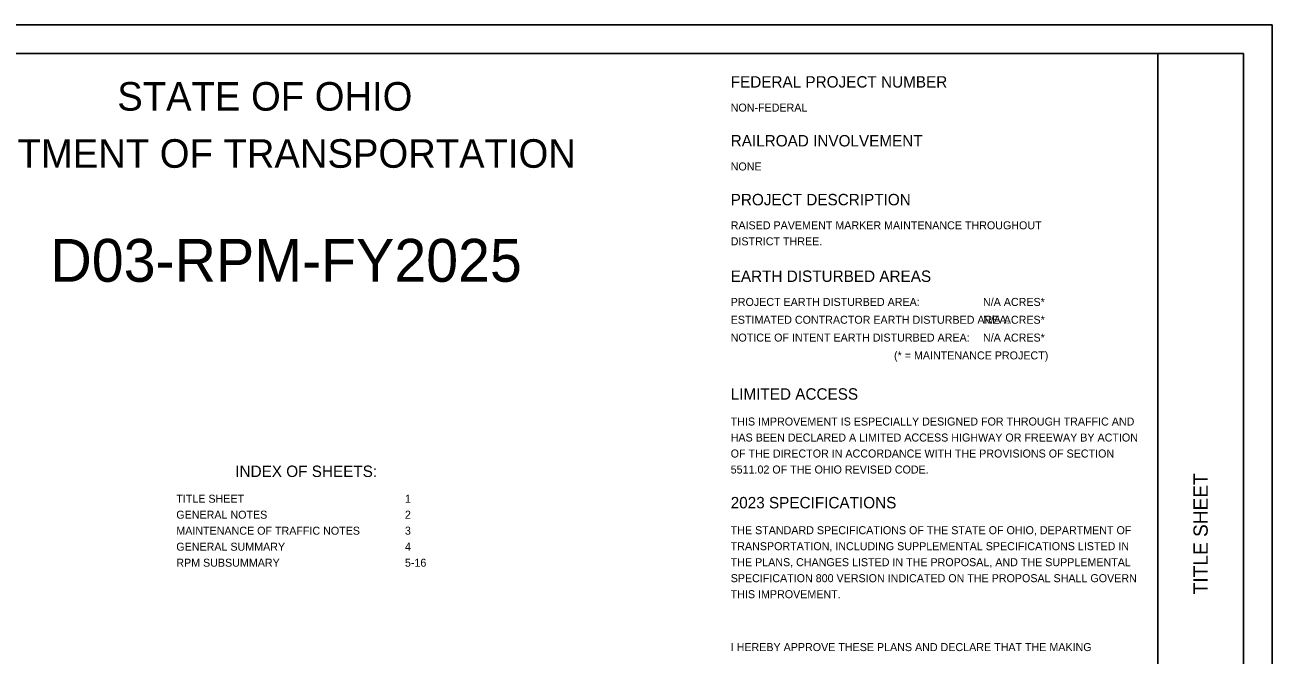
# Model space of a CAD drawing. Extents: x 0 to 34, y 0 to 22.
# Drawn here: x 12.18 to 34, y 10.97 to 22 of the extents above; entities that cross this region are included whole.
import ezdxf

# ---------------------------------------------------------------- set-up
doc = ezdxf.new("R2010")
doc.units = 0
for name, color, linetype in [('SH_Border', 7, 'Continuous'), ('SH_Cut_Line', 7, 'Continuous'), ('SH_Data', 7, 'Continuous'), ('SH_Text', 7, 'Continuous')]:
    doc.layers.add(name, color=color, linetype=linetype)

msp = doc.modelspace()

# ---------------------------------------------------------------- linework, layer by layer
at = {"layer": 'SH_Border'}
msp.add_line((32, 0.5), (32, 21.5), dxfattribs=at)
msp.add_lwpolyline([(1.5, 21.5), (33.5, 21.5), (33.5, 0.5), (1.5, 0.5)], close=True, dxfattribs=at)
at = {"layer": 'SH_Cut_Line'}
msp.add_lwpolyline([(0, 0), (34, 0), (34, 22), (0, 22)], close=True, dxfattribs=at)

# ---------------------------------------------------------------- texts
at = {"layer": 'SH_Data'}
msp.add_text('TITLE SHEET', height=0.25, rotation=90, dxfattribs=at).set_placement((32.875, 12.035))
at = {"layer": 'SH_Text'}
for s, height, p in [('STATE OF OHIO', 0.5, (13.795, 20.5)), ('FEDERAL PROJECT NUMBER', 0.2, (24.528, 20.903)), ('NON-FEDERAL', 0.14, (24.528, 20.483)), ('RAILROAD INVOLVEMENT', 0.2, (24.528, 19.873)), ('DEPARTMENT OF TRANSPORTATION', 0.5, (9.747, 19.5)), ('NONE', 0.14, (24.528, 19.453)), ('PROJECT DESCRIPTION', 0.2, (24.528, 18.843)), ('RAISED PAVEMENT MARKER MAINTENANCE THROUGHOUT', 0.14, (24.528, 18.423)), ('D03-RPM-FY2025', 0.75, (12.625, 17.505)), ('DISTRICT THREE.', 0.14, (24.528, 18.143)), ('EARTH DISTURBED AREAS', 0.2, (24.528, 17.502)), ('PROJECT EARTH DISTURBED AREA:', 0.14, (24.528, 17.082)), ('N/A ACRES*', 0.14, (28.942, 17.082)), ('ESTIMATED CONTRACTOR EARTH DISTURBED AREA:', 0.14, (24.528, 16.77)), ('N/A ACRES*', 0.14, (28.942, 16.77)), ('NOTICE OF INTENT EARTH DISTURBED AREA:', 0.14, (24.528, 16.458)), ('N/A ACRES*', 0.14, (28.942, 16.458)), ('(* = MAINTENANCE PROJECT)', 0.14, (27.386, 16.146)), ('LIMITED ACCESS', 0.2, (24.528, 15.441)), ('THIS IMPROVEMENT IS ESPECIALLY DESIGNED FOR THROUGH TRAFFIC AND', 0.14, (24.528, 14.989)), ('HAS BEEN DECLARED A LIMITED ACCESS HIGHWAY OR FREEWAY BY ACTION', 0.14, (24.528, 14.709)), ('OF THE DIRECTOR IN ACCORDANCE WITH THE PROVISIONS OF SECTION', 0.14, (24.528, 14.429)), ('INDEX OF SHEETS:', 0.2, (15.86, 14.088)), ('5511.02 OF THE OHIO REVISED CODE.', 0.14, (24.528, 14.149)), ('TITLE SHEET', 0.14, (14.828, 13.638)), ('1', 0.14, (18.828, 13.638)), ('2023 SPECIFICATIONS', 0.2, (24.528, 13.539)), ('GENERAL NOTES', 0.14, (14.828, 13.358)), ('2', 0.14, (18.828, 13.358)), ('MAINTENANCE OF TRAFFIC NOTES', 0.14, (14.828, 13.078)), ('3', 0.14, (18.828, 13.078)), ('THE STANDARD SPECIFICATIONS OF THE STATE OF OHIO, DEPARTMENT OF', 0.14, (24.528, 13.087)), ('GENERAL SUMMARY', 0.14, (14.828, 12.798)), ('4', 0.14, (18.828, 12.798)), ('TRANSPORTATION, INCLUDING SUPPLEMENTAL SPECIFICATIONS LISTED IN', 0.14, (24.528, 12.807)), ('RPM SUBSUMMARY', 0.14, (14.828, 12.518)), ('5-16', 0.14, (18.828, 12.518)), ('THE PLANS, CHANGES LISTED IN THE PROPOSAL, AND THE SUPPLEMENTAL', 0.14, (24.528, 12.527)), ('SPECIFICATION 800 VERSION INDICATED ON THE PROPOSAL SHALL GOVERN', 0.14, (24.528, 12.247)), ('THIS IMPROVEMENT.', 0.14, (24.528, 11.967)), ('I HEREBY APPROVE THESE PLANS AND DECLARE THAT THE MAKING', 0.14, (24.528, 11.041))]:
    msp.add_text(s, height=height, dxfattribs=at).set_placement(p)

doc.saveas('drawing.dxf')
